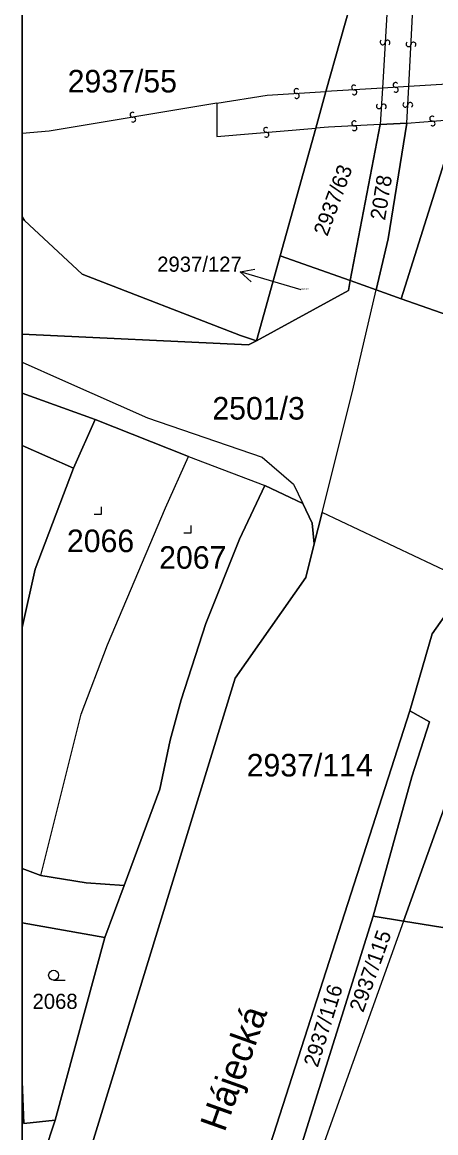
# Model space of a CAD drawing. Extents: x -596024 to -594475, y -1163820 to -1161957.
# Drawn here: x -596024.4 to -595993.3, y -1163306.5 to -1163222.9 of the extents above; entities that cross this region are included whole.
import ezdxf

# ---------------------------------------------------------------- set-up
doc = ezdxf.new("R2010")
doc.units = 0
for name, color, linetype in [('Level 1', 7, 'Continuous'), ('Level 11', 7, 'Continuous'), ('Level 13', 7, 'Continuous'), ('Level 3', 7, 'Continuous'), ('Level 4', 7, 'Continuous'), ('Level 5', 7, 'Continuous'), ('Level 57', 7, 'Continuous'), ('Level 60', 7, 'Continuous'), ('Vrstva 60', 7, 'Continuous'), ('Vrstva 63', 7, 'Continuous')]:
    doc.layers.add(name, color=color, linetype=linetype)

msp = doc.modelspace()

# ---------------------------------------------------------------- linework, layer by layer
at = {"layer": 'Level 1'}
for p, q in [((-596018.93, -1163252.82), (-596024.42, -1163250.838)), ((-596020.56, -1163256.47), (-596024.42, -1163254.759)), ((-596024.42, -1163286.627), (-596023.02, -1163287.15)), ((-596024.42, -1163290.702), (-596018.21, -1163291.81)), ((-596024.42, -1163313.094), (-596021.95, -1163305.57))]:
    msp.add_line(p, q, dxfattribs=at)
for points in [[(-595999.45, -1163220.46), (-596001.59, -1163228.13)], [(-596001.59, -1163228.13), (-596002.35, -1163230.88)], [(-595999.76, -1163242.36), (-595997.5, -1163230.6)], [(-595995.5, -1163230.5), (-595996.9, -1163239.2), (-595997.81, -1163243.06)], [(-595997.5, -1163230.6), (-595995.5, -1163230.5)], [(-595991.67, -1163230.19), (-595995.92, -1163243.73)], [(-596002.35, -1163230.88), (-596005.03, -1163240.49)], [(-596024.42, -1163237.562), (-596024.24, -1163237.84), (-596019.92, -1163241.88), (-596008.01, -1163246.48), (-596006.81, -1163246.88)], [(-596005.03, -1163240.49), (-596006.81, -1163246.88)], [(-595999.76, -1163242.36), (-596005.03, -1163240.49)], [(-596006.81, -1163246.88), (-595999.9, -1163243.1), (-595999.76, -1163242.36)], [(-595999.76, -1163242.36), (-595997.81, -1163243.06)], [(-596001.88, -1163259.82), (-595999.6, -1163250.7), (-595999.29, -1163249.39), (-595997.81, -1163243.06)], [(-595995.92, -1163243.73), (-595997.81, -1163243.06)], [(-595995.92, -1163243.73), (-595986.49, -1163247.05)], [(-596024.42, -1163246.401), (-596007.4, -1163247.2), (-596006.81, -1163246.88)], [(-596020.56, -1163256.47), (-596018.93, -1163252.82)], [(-596018.93, -1163252.82), (-596011.93, -1163255.61)], [(-596023.02, -1163287.15), (-596019.98, -1163274.99), (-596018.01, -1163269.77), (-596013.65, -1163259.46), (-596011.93, -1163255.61)], [(-596011.93, -1163255.61), (-596006.18, -1163257.79)], [(-596020.56, -1163256.47), (-596023.46, -1163264.08), (-596024.42, -1163268.481)], [(-596016.76, -1163287.9), (-596014.08, -1163280.65), (-596013.3, -1163276.96), (-596012.48, -1163273.92), (-596010.62, -1163268.17), (-596008.08, -1163261.82), (-596006.18, -1163257.79)], [(-596006.18, -1163257.79), (-596003.32, -1163259.14)], [(-596003.32, -1163259.14), (-596002.61, -1163260.62), (-596002.47, -1163262.17)], [(-596002.47, -1163262.17), (-596001.88, -1163259.82)], [(-595990.84, -1163265.04), (-596001.88, -1163259.82)], [(-596024.42, -1163324.507), (-596008.4, -1163272.3), (-596003.1, -1163264.7), (-596002.47, -1163262.17)], [(-595990.84, -1163265.04), (-595993.6, -1163268.94), (-595995.27, -1163274.75)], [(-595980.96, -1163268.62), (-595987.4, -1163272.7), (-595992.1, -1163280.4), (-595995.75, -1163290.59)], [(-595995.75, -1163290.59), (-595988.59, -1163291.75), (-595982.29, -1163274.51), (-595981.24, -1163269.88)], [(-595995.27, -1163274.75), (-596018.1, -1163345.8)], [(-595998.04, -1163290.22), (-595995.12, -1163279.72), (-595993.79, -1163275.57), (-595995.27, -1163274.75)], [(-596023.02, -1163287.15), (-596019.61, -1163287.7), (-596016.76, -1163287.9)], [(-596016.76, -1163287.9), (-596018.21, -1163291.81)], [(-596009.16, -1163325.77), (-595998.04, -1163290.22)], [(-595995.75, -1163290.59), (-596006.1, -1163319.5), (-596009.16, -1163325.77)], [(-595998.04, -1163290.22), (-595995.75, -1163290.59)], [(-596018.21, -1163291.81), (-596021.95, -1163305.57)], [(-596021.95, -1163305.57), (-596024.3, -1163305.81), (-596024.42, -1163302.667)]]:
    msp.add_lwpolyline(points, dxfattribs=at)
at = {"layer": 'Level 13'}
for centre, start, end in [((-595997.324, -1163224.418), 123.74788, 356.33788), ((-595996.956, -1163224.443), 303.96234, 176.06034), ((-595995.374, -1163224.559), 124.4025, 356.5005), ((-595995.006, -1163224.58), 304.18805, 176.77805), ((-596003.8, -1163228.086), 40.87626, 272.97426), ((-595999.47, -1163227.816), 40.65907, 273.24907), ((-595999.45, -1163228.184), 220.87353, 92.97152), ((-595996.35, -1163227.626), 40.60912, 273.19912), ((-595996.331, -1163227.994), 220.82358, 92.92158), ((-596003.78, -1163228.454), 220.66181, 93.25181), ((-595995.614, -1163229.108), 124.2506, 356.3486), ((-595995.246, -1163229.131), 304.03615, 176.62615), ((-596016.129, -1163229.868), 46.6206, 279.2106), ((-595997.604, -1163229.228), 123.80412, 356.39412), ((-595997.236, -1163229.252), 304.01858, 176.11657), ((-596016.071, -1163230.232), 226.83506, 98.93305), ((-595999.459, -1163230.516), 40.09395, 272.68395), ((-595999.442, -1163230.884), 220.30841, 92.4064), ((-595993.593, -1163230.156), 42.00016, 274.09816), ((-595993.566, -1163230.524), 221.78571, 94.37571), ((-596006.084, -1163231.006), 42.13001, 274.22801), ((-596006.056, -1163231.373), 221.91556, 94.50556)]:
    msp.add_arc(centre, 0.184, start, end, dxfattribs=at)
at = {"layer": 'Level 3'}
for points in [[(-595996.93, -1163220.99), (-595997.34, -1163227.87)], [(-595995.35, -1163227.75), (-595995.02, -1163221.39)], [(-596009.8, -1163229), (-596006, -1163228.4), (-596001.59, -1163228.13)], [(-595997.34, -1163227.87), (-596001.59, -1163228.13)], [(-595997.34, -1163227.87), (-595997.5, -1163230.6)], [(-595995.35, -1163227.75), (-595997.34, -1163227.87)], [(-595995.5, -1163230.5), (-595995.35, -1163227.75)], [(-595990.82, -1163227.47), (-595995.35, -1163227.75)], [(-596009.8, -1163229), (-596022.4, -1163231.1), (-596024.42, -1163231.272)], [(-596009.8, -1163229), (-596009.8, -1163231.5), (-596002.35, -1163230.88)], [(-595997.5, -1163230.6), (-596001.4, -1163230.8), (-596002.35, -1163230.88)], [(-595995.5, -1163230.5), (-595991.67, -1163230.19)], [(-596024.42, -1163248.507), (-596021.39, -1163249.84), (-596015, -1163252.7), (-596006.38, -1163255.64), (-596004.03, -1163257.67), (-596003.32, -1163259.14)]]:
    msp.add_lwpolyline(points, dxfattribs=at)
at = {"layer": 'Level 5'}
msp.add_line((-596022.06, -1163295.03), (-596021.185, -1163295.03), dxfattribs=at)
for points in [[(-596019.02, -1163259.94), (-596018.47, -1163259.94), (-596018.47, -1163259.39)], [(-596012.28, -1163261.34), (-596011.73, -1163261.34), (-596011.73, -1163260.79)]]:
    msp.add_lwpolyline(points, dxfattribs=at)
msp.add_circle((-596022.06, -1163294.655), 0.375, dxfattribs=at)
at = {"layer": 'Level 57'}
for p, q in [((-596005.153, -1163242.54), (-596008.03, -1163241.69)), ((-596003.46, -1163243.04), (-596005.153, -1163242.54))]:
    msp.add_line(p, q, dxfattribs=at)
msp.add_lwpolyline([(-596007.213, -1163242.453), (-596008.03, -1163241.69), (-596006.929, -1163241.494)], dxfattribs=at)
at = {"layer": 'Level 60'}
for points in [[(-595996.9, -1163239.2), (-595995.5, -1163230.5), (-595997.5, -1163230.6), (-595999.76, -1163242.36), (-596005.03, -1163240.49), (-596002.35, -1163230.88), (-596001.59, -1163228.13), (-595999.45, -1163220.46), (-595996.93, -1163220.99), (-595995.02, -1163221.39), (-595989.3, -1163222.59), (-595990.04, -1163224.98), (-595990.82, -1163227.47), (-595991.67, -1163230.19), (-595995.92, -1163243.73), (-595997.81, -1163243.06)], [(-595990.04, -1163224.98), (-595986.71, -1163226.22), (-595986.99, -1163227.1), (-595987.87, -1163229.88), (-595988.4, -1163231.54), (-595982.13, -1163233.66), (-595986.49, -1163247.05), (-595995.92, -1163243.73), (-595991.67, -1163230.19), (-595990.82, -1163227.47)], [(-595995.5, -1163230.5), (-595996.9, -1163239.2), (-595997.81, -1163243.06), (-595999.76, -1163242.36), (-595997.5, -1163230.6)], [(-595999.9, -1163243.1), (-596006.81, -1163246.88), (-596005.03, -1163240.49), (-595999.76, -1163242.36)], [(-596019.61, -1163287.7), (-596023.02, -1163287.15), (-596019.98, -1163274.99), (-596018.01, -1163269.77), (-596013.65, -1163259.46), (-596011.93, -1163255.61), (-596006.18, -1163257.79), (-596008.08, -1163261.82), (-596010.62, -1163268.17), (-596012.48, -1163273.92), (-596013.3, -1163276.96), (-596014.08, -1163280.65), (-596016.76, -1163287.9)], [(-595987.4, -1163272.7), (-595992.1, -1163280.4), (-595995.75, -1163290.59), (-595998.04, -1163290.22), (-595995.12, -1163279.72), (-595993.79, -1163275.57), (-595995.27, -1163274.75), (-595993.6, -1163268.94), (-595990.84, -1163265.04), (-595980.96, -1163268.62)], [(-595992.1, -1163280.4), (-595987.4, -1163272.7), (-595980.96, -1163268.62), (-595981.24, -1163269.88), (-595982.29, -1163274.51), (-595988.59, -1163291.75), (-595995.75, -1163290.59)], [(-596012.2, -1163332), (-596016.6, -1163342), (-596018.1, -1163345.8), (-595995.27, -1163274.75), (-595993.79, -1163275.57), (-595995.12, -1163279.72), (-595998.04, -1163290.22), (-596009.16, -1163325.77)], [(-595995.75, -1163290.59), (-596006.1, -1163319.5), (-596009.16, -1163325.77), (-595998.04, -1163290.22)]]:
    msp.add_lwpolyline(points, close=True, dxfattribs=at)
msp.add_lwpolyline([(-595990.84, -1163265.04), (-596001.88, -1163259.82), (-595999.6, -1163250.7), (-595999.29, -1163249.39), (-595997.81, -1163243.06), (-595995.92, -1163243.73), (-595986.49, -1163247.05)], dxfattribs=at)
at = {"layer": 'Vrstva 60'}
for points in [[(-596024.42, -1163216.329), (-596024.42, -1163237.562), (-596024.24, -1163237.84), (-596019.92, -1163241.88), (-596008.01, -1163246.48), (-596006.81, -1163246.88), (-596005.03, -1163240.49), (-596002.35, -1163230.88), (-596001.59, -1163228.13), (-595999.45, -1163220.46), (-596001.45, -1163220.11), (-596014.8, -1163217.74), (-596017.35, -1163217.34), (-596022.73, -1163216.5)], [(-596024.42, -1163237.562), (-596024.42, -1163246.401), (-596007.4, -1163247.2), (-596006.81, -1163246.88), (-596008.01, -1163246.48), (-596019.92, -1163241.88), (-596024.24, -1163237.84)], [(-596024.42, -1163246.401), (-596024.42, -1163250.838), (-596018.93, -1163252.82), (-596011.93, -1163255.61), (-596006.18, -1163257.79), (-596003.32, -1163259.14), (-596002.61, -1163260.62), (-596002.47, -1163262.17), (-596001.88, -1163259.82), (-595999.6, -1163250.7), (-595999.29, -1163249.39), (-595997.81, -1163243.06), (-595999.76, -1163242.36), (-595999.9, -1163243.1), (-596006.81, -1163246.88), (-596007.4, -1163247.2)], [(-596024.42, -1163250.838), (-596024.42, -1163254.759), (-596020.56, -1163256.47), (-596018.93, -1163252.82)], [(-596024.42, -1163268.481), (-596024.42, -1163286.627), (-596023.02, -1163287.15), (-596019.98, -1163274.99), (-596018.01, -1163269.77), (-596013.65, -1163259.46), (-596011.93, -1163255.61), (-596018.93, -1163252.82), (-596020.56, -1163256.47), (-596023.46, -1163264.08)], [(-596024.42, -1163254.759), (-596024.42, -1163268.481), (-596023.46, -1163264.08), (-596020.56, -1163256.47)], [(-596024.42, -1163313.094), (-596024.42, -1163324.507), (-596008.4, -1163272.3), (-596003.1, -1163264.7), (-596002.47, -1163262.17), (-596002.61, -1163260.62), (-596003.32, -1163259.14), (-596006.18, -1163257.79), (-596008.08, -1163261.82), (-596010.62, -1163268.17), (-596012.48, -1163273.92), (-596013.3, -1163276.96), (-596014.08, -1163280.65), (-596016.76, -1163287.9), (-596018.21, -1163291.81), (-596021.95, -1163305.57)], [(-596024.42, -1163324.507), (-596024.42, -1163355.134), (-596023.9, -1163355.2), (-596020.1, -1163345.4), (-596018.1, -1163345.8), (-595995.27, -1163274.75), (-595993.6, -1163268.94), (-595990.84, -1163265.04), (-596001.88, -1163259.82), (-596002.47, -1163262.17), (-596003.1, -1163264.7), (-596008.4, -1163272.3)], [(-596024.42, -1163379.684), (-596024.42, -1163445.396), (-596010.79, -1163464.74), (-595992.89, -1163374.07), (-596000.1, -1163357.39), (-595981.24, -1163347.43), (-595981.35, -1163347.21), (-595982.82, -1163343.22), (-595989.61, -1163344.68), (-595988.46, -1163335.19), (-595980.27, -1163309.7), (-595990.92, -1163294.01), (-595965.02, -1163276.18), (-595954.16, -1163291.68), (-595947.48, -1163285.95), (-595946.19, -1163282.81), (-595981.24, -1163269.88), (-595982.29, -1163274.51), (-595988.59, -1163291.75), (-595995.75, -1163290.59), (-596006.1, -1163319.5), (-596009.16, -1163325.77), (-596019.9, -1163360.11), (-596022.6, -1163375.54)], [(-596024.42, -1163290.702), (-596018.21, -1163291.81), (-596016.76, -1163287.9), (-596019.61, -1163287.7), (-596023.02, -1163287.15), (-596024.42, -1163286.627)], [(-596024.42, -1163290.702), (-596024.42, -1163302.667), (-596024.3, -1163305.81), (-596021.95, -1163305.57), (-596018.21, -1163291.81)], [(-596024.42, -1163313.094), (-596021.95, -1163305.57), (-596024.3, -1163305.81), (-596024.42, -1163302.667)]]:
    msp.add_lwpolyline(points, close=True, dxfattribs=at)
at = {"layer": 'Vrstva 63'}
msp.add_lwpolyline([(-594475.47, -1163820.23), (-596024.42, -1163820.23), (-596024.42, -1161956.88), (-594475.47, -1161956.88)], close=True, dxfattribs=at)

# ---------------------------------------------------------------- texts
at = {"layer": 'Level 11'}
msp.add_text('Hájecká', height=2, rotation=70.42056, dxfattribs=at).set_placement((-596009.207, -1163306.531))
at = {"layer": 'Level 4'}
for s, height, p in [('2937/55', 1.7, (-596021.005, -1163228.19)), ('2937/127', 0.1, (-596003.46, -1163243.04)), ('2501/3', 1.7, (-596010.127, -1163252.82)), ('2066', 1.7, (-596021.061, -1163262.8)), ('2067', 1.7, (-596014.126, -1163264.05)), ('2937/114', 1.7, (-596007.546, -1163279.69)), ('2068', 1.14, (-596023.646, -1163297.19))]:
    msp.add_text(s, height=height, dxfattribs=at).set_placement(p)
for s, rotation, p in [('2937/63', 69.705, (-596001.484, -1163239.079)), ('2078', 80.85834, (-595997.145, -1163237.862)), ('2937/115', 70.30224, (-595998.786, -1163297.514)), ('2937/116', 72.63036, (-596002.205, -1163301.645))]:
    msp.add_text(s, height=1.14, rotation=rotation, dxfattribs=at).set_placement(p)
at = {"layer": 'Level 57'}
msp.add_text('2937/127', height=1.14, dxfattribs=at).set_placement((-596014.273, -1163241.69))

doc.saveas('drawing.dxf')
